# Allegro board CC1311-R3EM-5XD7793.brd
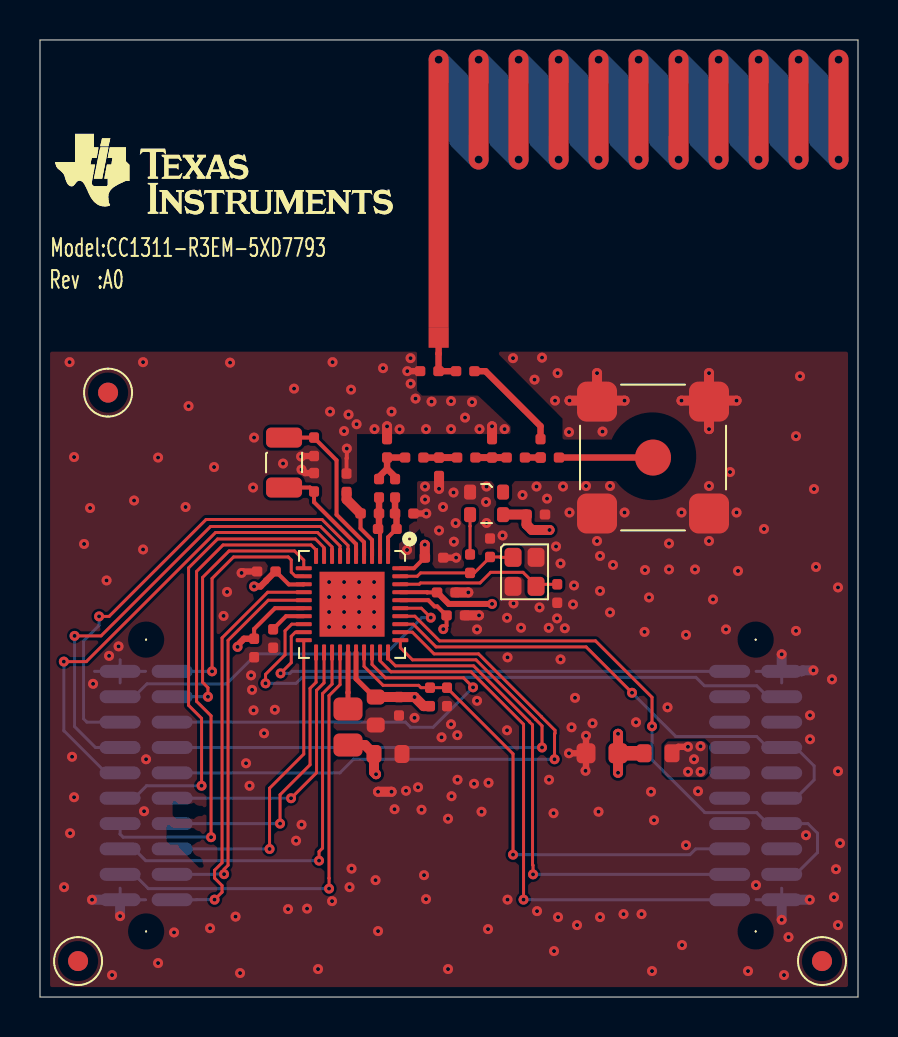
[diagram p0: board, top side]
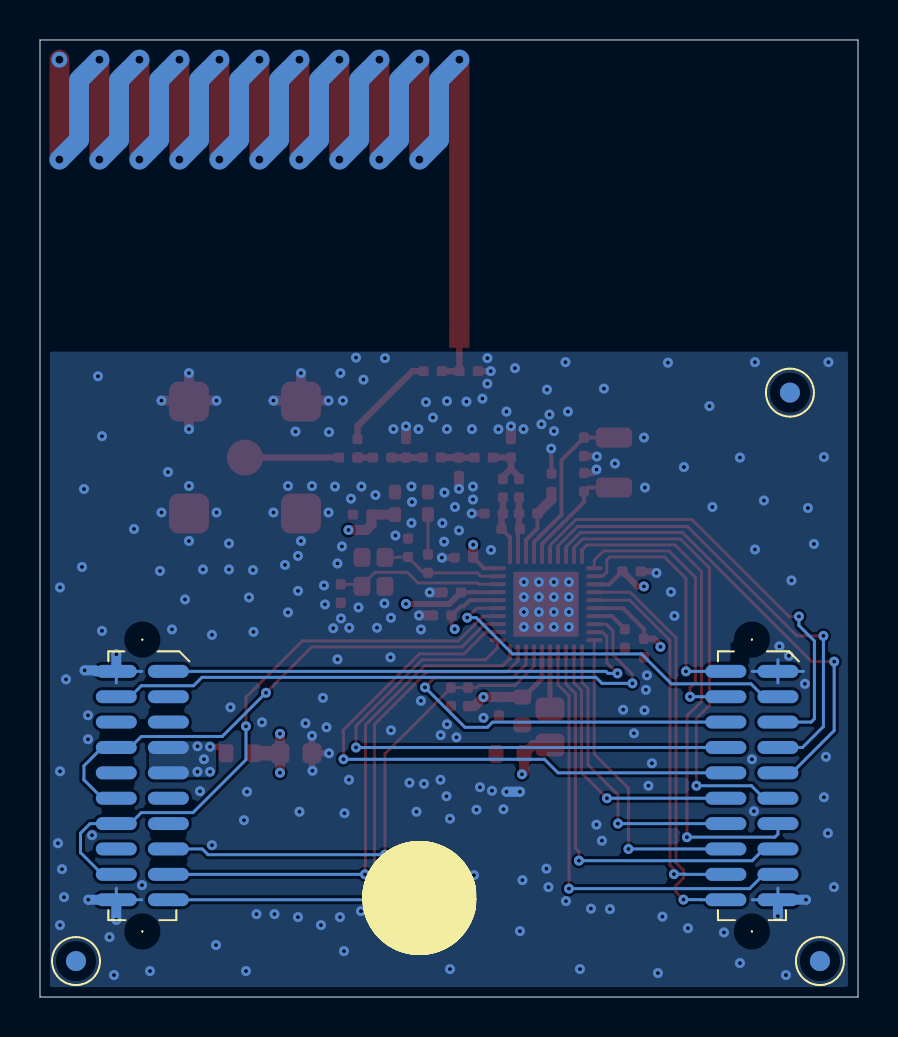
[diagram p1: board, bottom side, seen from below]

Outline 40.9 x 47.9 mm; copper layers: TOP, L2, L3, BOTTOM. Coordinates in mm from the lower left corner of the outline.
Outline path: 0,47.9 0,0 40.9,0 40.9,47.9 0,47.9

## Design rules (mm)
constraint set DEFAULT: min track width 0.15

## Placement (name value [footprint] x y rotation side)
A1  Antenna PCB helix 868/915MHz  [ANTENNA868_915MHZ_A2N]  19.93 32.99 0 top
C1  22uF  [CAPC1608X100A2N#2]  28.9 12.2 180 top
C11  3.6pF  [CAPC1005X60B2N]  17.75 24.2 0 top
C12  2.7pF  [CAPC1005X60B2N]  17.35 27 90 top
C13  6.2pF  [CAPC1005X60B2N]  19.95 26.08 90 top
C14  3pF  [CAPC1005X60B2N]  22.6 27.92 270 top
C15  100pF  [CAPC1005X60B2N]  24.25 27 180 top
C21  100pF  [CAPC1005X60B2N]  15.33 26.2 270 top
C22  3.6pF  [CAPC1005X60B2N]  16.95 25 90 top
C41  12pF  [CAPC1005X60B2N]  13.7 28 270 top
C51  12pF  [CAPC1005X60B2N]  13.7 25.3 90 top
C131  0.1uF  [CAPC1005X60B2N]  11.78 21.3 180 top
C221  0.1uF  [CAPC1005X60B2N]  10.71 17.93 270 top
C231  1uF  [CAPC1005X60B2N]  11.66 18.41 270 top
C331  22uF  [CAPC1608X100A2N]  16.7 12.16 0 top
C341  22uF  [CAPC1608X100A2N]  16.79 15.02 270 top
C342  0.1uF  [CAPC1005X60B2N]  17.95 15.01 270 top
C351  0.1uF  [CAPC1005X60B2N]  20.35 15.48 270 top
C441  0.1uF  [CAPC1005X60B2N]  20.33 19.1 0 top
C451  0.1uF  [CAPC1005X60B2N]  19.85 20.25 0 top
C461  7.5pF  [CAPC1005X60B2N]  25.86 20.66 270 top
C471  0.1uF  [CAPC1005X60B2N]  21.5 22.15 270 top
C472  0.1uF  [CAPC1005X60B2N]  24.33 24.15 0 top
C473  7.5pF  [CAPC1005X60B2N]  22.5 22.02 90 top
C481  0.1uF  [CAPC1005X60B2N]  19.24 21.99 0 top
FIDU1  FIDU_1MM  [FID100X115B]  1.9 1.8 0 top
FIDU2  FIDU_1MM  [FID100X115B]  39.1 1.8 0 top
FIDU3  FIDU_1MM  [FID100X115B]  3.4 30.25 0 top
FIDU4  FIDU_1MM  [FID100X115B]  1.9 1.8 180 bottom
FIDU5  FIDU_1MM  [FID100X115B]  39.1 1.8 180 bottom
FIDU6  FIDU_1MM  [FID100X115B]  3.4 30.25 180 bottom
FL1  BLM18HE152SN1  [FIL_BLM18HE152SN1DN]  30.2 12.2 0 top
J1  SMA-10V21-TGG  [HUSTSAN_SMA10V21TGGAN]  30.65 27 0 top
L11  27nH  [INDC1005X60D2N]  17.83 23.42 180 top
L12  7.5nH  [INDC1005X60D2N]  17.76 25 90 top
L13  6.8nH  [INDC1005X60D2N]  18.25 27 0 top
L14  6.8nH  [INDC1005X60D2N]  20.85 27 0 top
L15  1nH  [INDC1005X60D2N]  19.93 31.33 180 top
L21  7.5nH  [INDC1005X60D2N]  16.95 24.2 180 top
L331  6.8uH  [INDC2012X150A2N]  15.4 14.41 270 top
NOREF  -  []  1.75 43.2 0 top
NOREF#2  -  []  0 44.02 0 top
NOREF#3  -  []  29.31 0 90 top
NOREF#4  -  []  25.1 1.92 180 bottom
P1  SFM-110-02-S-D-A-K  [SAMTEC_SFM11002AN]  4 16.3 0 bottom
P2  SFM-110-02-S-D-A-K  [SAMTEC_SFM11002AN]  34.48 16.3 0 bottom
R11  0  [RESC1005X40B2N]  25.95 27 180 top
R12  0  [RESC1005X40B2N]  25.03 27 90 top
R13  0  [RESC1005X40B2N]  20.8 31.32 0 top
R351  100k  [RESC1005X40B2N]  19.5 15.48 270 top
U1  CC1311R31T0RKPR  [QFNFC40P500X500X100-41A2N]  17.4 22.08 180 top
Y1  32.768kHz  [XTAL_TZ1166C_B2N]  12.2 28 270 top
Y2  48MHz  [OSCCC200X160X50-4A2N]  23.66 22 270 top
Y3  48MHz  [OSC_TG2016SBN_A2N]  23.16 25.27 180 top

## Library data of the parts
A1 = ANTENNA: User Part Number: #PN
C1 C331 C341 = CAPACITOR: User Part Number: #PN; alternate symbols: (CAPC1608X100A2L,CAPC1608X100A2M)
C11-C15 C21 C22 C41 C51 C131 C221 C231 C342 C351 C441 C451 C461 C471-C473 C481 = CAPACITOR: User Part Number: #PN
FIDU1-FIDU6 = FIDMARK
FL1 = FILTER_2PIN: alternate symbols: (FIL_BLM18HE152SN1DL,FIL_BLM18HE152SN1DM)
J1 = CONN_COAX_1+4: alternate symbols: (HUSTSAN_SMA10V21TGGL,HUSTSAN_SMA10V21TGGM)
L11-L14 L21 = INDUCTOR_HOR_1_2: User Part Number: #PN
L15 = INDUCTOR_HOR_1_2: User Part Number: #PN; alternate symbols: (INDC1005X60C2L,INDC1005X60C2M)
L331 = INDUCTOR: User Part Number: #PN; alternate symbols: (INDC2012X150A2L,INDC2012X150A2M)
P1 P2 = CONN_HEADER_2X10_P_S: alternate symbols: (SAMTEC_SFM11002AL,SAMTEC_SFM11002AM)
R11-R13 R351 = RESISTOR: User Part Number: #PN
U1 = IC_RF_CC1311R1F32TRKPR_VQFN40: User Part Number: #PN; alternate symbols: (QFNFC40P500X500X100-41A2L,QFNFC40P500X500X100-41A2M)
Y1 = XTAL: User Part Number: #PN; alternate symbols: (XTAL_TZ1166C_B2L,XTAL_TZ1166C_B2M)
Y2 = XTAL_4_V3: User Part Number: #PN; alternate symbols: (OSCCC200X160X50-4A2L,OSCCC200X160X50-4A2M)
Y3 = XTAL_GEN: User Part Number: #PN; alternate symbols: (OSC_TG2016SBN_A2L,OSC_TG2016SBN_A2M)

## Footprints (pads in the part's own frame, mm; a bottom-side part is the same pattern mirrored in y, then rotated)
ANTENNA868_915MHZ_A2N
  rect 1x1 smd: 1(0,0)
CAPC1005X60B2N
  custom 0.125x0.125 smd: 1(0,0) 2(0.924,0)
CAPC1608X100A2N
  custom 0.188x0.188 smd: 1(0,0) 2(1.4,0)
CAPC1608X100A2N#2
  custom 0.237x0.237 smd: 1(0,0) 2(1.6,0)
FID100X115B
  round 1 smd: 1(0,0)
FIL_BLM18HE152SN1DN
  custom 0.188x0.188 smd: 1(0,0) 2(1.4,0)
HUSTSAN_SMA10V21TGGAN
  round 1.801 smd: 1(0,0)
  custom 0.5x0.5 smd: 2(-2.8,-2.8) 3(2.8,-2.8) 4(2.8,2.8) 5(-2.8,2.8)
INDC1005X60D2N
  custom 0.125x0.125 smd: 1(0,0) 2(0.924,0)
INDC2012X150A2N
  custom 0.287x0.287 smd: 1(0,0) 2(1.8,0)
OSC_TG2016SBN_A2N
  custom 0.15x0.15 smd: 1(0,0) 2(1.65,0) 3(1.65,1.13) 4(0,1.13)
OSCCC200X160X50-4A2N
  custom 0.212x0.212 smd: 1(0,0) 2(1.45,0) 3(1.45,1.15) 4(0,1.15)
QFNFC40P500X500X100-41A2N
  custom 0.05x0.05 smd: 1(0,0) 2(0.4,0) 3(0.8,0) 4(1.2,0) 5(1.6,0) 6(2,0) 7(2.4,0) 8(2.8,0) 9(3.2,0) 10(3.6,0) 11(4.215,0.615) 12(4.215,1.015) 13(4.215,1.415) 14(4.215,1.815) 15(4.215,2.215) 16(4.215,2.615) 17(4.215,3.015) 18(4.215,3.415) 19(4.215,3.815) 20(4.215,4.215) 21(3.6,4.83) 22(3.2,4.83) 23(2.8,4.83) 24(2.4,4.83) 25(2,4.83) 26(1.6,4.83) 27(1.2,4.83) 28(0.8,4.83) 29(0.4,4.83) 30(0,4.83) 31(-0.615,4.215) 32(-0.615,3.815) 33(-0.615,3.415) 34(-0.615,3.015) 35(-0.615,2.615) 36(-0.615,2.215) 37(-0.615,1.815) 38(-0.615,1.415) 39(-0.615,1.015) 40(-0.615,0.615)
  rect 3.25x3.25 smd: 41(1.8,2.415)
RESC1005X40B2N
  custom 0.125x0.125 smd: 1(0,0) 2(0.924,0)
SAMTEC_SFM11002AN
  round 0.099 hole 1.501 unplated: (1.302,-1.588) (1.302,13.017)
  oval 2.05x0.65 smd: 1(0,0) 2(2.604,0) 3(0,1.27) 4(2.604,1.27) 5(0,2.54) 6(2.604,2.54) 7(0,3.81) 8(2.604,3.81) 9(0,5.08) 10(2.604,5.08) 11(0,6.35) 12(2.604,6.35) 13(0,7.62) 14(2.604,7.62) 15(0,8.89) 16(2.604,8.89) 17(0,10.16) 18(2.604,10.16) 19(0,11.43) 20(2.604,11.43)
XTAL_TZ1166C_B2N
  custom 0.25x0.25 smd: 1(0,0) 2(2.5,0)

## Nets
GND: C1.2 C11.2 C12.2 C13.1 C14.1 C21.1 C41.2 C51.2 C131.2 C221.2 C231.2 C331.2 C341.2 C342.2 C351.2 C441.2 C451.2 C461.2 C472.2 C473.2 C481.2 J1.2 J1.3 J1.4 J1.5 L15.2 P1.1 P1.19 P2.2 P2.20 U1.41 Y2.2 Y2.4(GND#4) Y3.2
VDD_EB: FL1.2 P2.7 P2.9
VDDR: C331.1 C451.1 C481.1 L331.2 U1.37 U1.40
VDDS: C1.1 C131.1 C221.1 C341.1 C342.1 C441.1 C472.1 FL1.1 R351.2 U1.13 U1.16 U1.26 U1.36 Y3.4(VDD)
DCDC_SW: L331.1 U1.25
DIO_1: P1.5 U1.6
DIO_2: P1.7 U1.7
DIO_3: P1.9 U1.8
DIO_4: P1.11 U1.9
DIO_5: P1.13 U1.10
DIO_6: P1.4 U1.11
DIO_7: P1.2 U1.12
DIO_8: P1.20 U1.14
DIO_9: P1.18 U1.15(DIO_9)
DIO_10: P1.16 U1.20
DIO_11: P1.14 U1.21
DIO_12: P1.12 U1.22
DIO_13: P1.15 U1.23
DIO_14: P1.17 U1.24
DIO_15: P1.6 U1.28
DIO_16 / JTAG TDO: P2.19 U1.29
DIO_17 / JTAG TDI: P2.17 U1.30
DIO_18: P1.8 U1.31
DIO_19: P1.10 U1.32
DIO_20: P2.8 P2.12 U1.33
DIO_21: P2.14 P2.18 U1.34
DIO_22: P1.3 U1.35
JTAG_TCK: P2.1 U1.19
JTAG_TMS: P2.4 U1.18
NRESET: C351.1 P2.15 R351.1 U1.27
N485531: J1.1 R11.1
N485535: A1.1(FEED/GND_1) L15.1 R13.1
N485643: C22.1 L11.2 L21.1 U1.2
N485645: C11.1 L11.1 L12.1 U1.1
N485661: C12.1 C22.2 L12.2 L13.1
N485675: C13.2 L13.2 L14.1
N485699: C231.1 U1.17
N485701: C41.1 U1.4 Y1.1
N485707: C51.1 U1.5 Y1.2
N485827: C14.2 C15.2 L14.2
N485893: C15.1 R11.2 R12.1
N485901: R12.2 R13.2
N485927: C21.2 L21.2 U1.3
N485947: C461.1 U1.38 Y2.3
N499675: C471.2 C473.1 U1.39 Y2.1
N509134: C471.1 Y3.3

Pads without a net: FIDU1 1; FIDU2 1; FIDU3 1; FIDU4 1; FIDU5 1; FIDU6 1; P2 3 5 6 10 11 13 16; Y3 1

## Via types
v1: diameter 0.5, hole 0.2, TOP to BOTTOM, 281 vias
v2: diameter 0.8, hole 0.4, TOP to BOTTOM, 21 vias

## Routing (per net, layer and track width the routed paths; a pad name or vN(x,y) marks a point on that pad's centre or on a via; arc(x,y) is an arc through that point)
GND: length 40
  TOP w0.2: v1(15.34,27.45) 15.34,26.97 15.33,26.96 C21.1
  TOP w0.32: C51.2 13.25,26.22 v1(13.08,26.4) ; v1(27.3,13.08) C1.2 ; C1.2 v1(26.45,12.2) ; C1.2 27.3,11.35 v1(27.28,11.32) ; C131.2 10.15,21.3 v1(10.08,21.22) ; C41.2 13.08,27.08 v1(13.06,27.05) ; L15.2 v1(18.37,31.33) ; C481.2 v1(20.81,21.99) ; C11.2 v1(19.32,24.2)
  TOP w0.5: C12.2 v1(17.35,28.56) ; v1(32.08,29.85) 33.45,29.85 ; 33.45,29.85 v1(34.83,29.85) ; 33.45,29.85 v1(33.45,31.23) ; 33.45,29.85 J1.4 v1(33.45,28.42) ; 21.25,19.1 v1(21.95,19.1) ; 27.85,29.85 v1(29.23,29.85) ; 27.85,29.85 v1(27.85,31.23) ; 27.85,29.85 v1(26.48,29.85) ; v1(16.9,10.27) v1(17.58,10.27) ; C451.2 v1(21.42,20.25) ; C13.1 v1(19.95,25.44) ; C14.1 v1(22.6,28.56)
  L2 w0.5: v1(16.9,10.27) v1(17.58,10.27)
  L3 w0.5: v1(16.9,10.27) v1(17.58,10.27)
  BOTTOM w0.15: P1.1 5.28,16.3 ; P1.1 2.73,16.3 ; P1.1 4,16.88 ; P1.1 4,15.72 ; 5.28,4.87 P1.19 4,5.45 ; 35.81,4.87 P2.20 37.09,5.45 ; 35.81,16.3 P2.2 37.09,15.72
  BOTTOM w0.5: v1(37.09,3.87) P2.20 v1(38.49,4.87) ; v1(4,4.05) P1.19 v1(2.6,4.87) ; v1(16.9,10.27) v1(17.58,10.27) ; v1(38.67,16.35) 38.13,16.35 38.08,16.3 P2.2 v1(37.09,17.15)
  vias: v1(1.2,5.5) v1(1.48,31.77) v1(1.5,8.2) v1(1.6,12.02) v1(1.7,27.02) v1(1.7,10) v1(2.2,22.67) v1(2.5,24.47) v1(2.65,15.67) v1(3.33,20.85) v1(3.45,17.08) v1(3.6,1.1) v1(3.93,17.55) v1(4.7,24.85) v1(5.15,31.77) v1(5.15,22.4) v1(5.2,9.3) v1(5.3,11.9) v1(5.9,27) v1(5.9,1.7) v1(6.7,3.23) v1(7.28,24.52) v1(7.43,29.58) v1(8.5,3.44) v1(8.7,26.52) v1(9.18,19.08) v1(9.35,20.27) v1(9.5,31.75) v1(9.78,4.02) v1(10,1.2) v1(10.3,11.7) v1(10.55,16.1) v1(10.48,10.58) v1(10.6,15.38) v1(10.7,28) v1(10.65,25.5) v1(10.68,14.35) v1(11.2,13.2) v1(11.74,14.38) v1(12.15,26.7) v1(12.4,4.4) v1(12.7,30.45) v1(12.8,7.83) v1(13.08,8.62) v1(13.35,4.42) v1(13.9,1.4) v1(14.5,29.3) v1(14.46,20.77) v1(14.46,20.02) v1(14.46,19.27) v1(14.46,18.52) v1(14.63,31.77) v1(14.6,4.8) v1(15.2,28.33) v1(15.21,20.77) v1(15.21,20.02) v1(15.21,19.27) v1(15.21,18.52) v1(15.43,29.15) v1(15.55,30.4) v1(15.48,5.5) v1(15.58,6.42) v1(15.83,28.67) v1(15.96,20.77) v1(15.96,20.02) v1(15.96,19.27) v1(15.96,18.52) v1(16.73,28.42) v1(16.71,20.77) v1(16.71,20.02) v1(16.71,19.27) v1(16.71,18.52) v1(16.78,5.85) v1(16.9,3.3) v1(17.15,31.47) v1(17.58,29.3) v1(17.73,9.4) v1(17.98,28.42) v1(18.35,22.38) v1(18.3,10.32) v1(18.53,31.97) v1(18.53,30.7) v1(18.73,13.97) v1(18.78,29.95) v1(18.9,10.5) v1(19.08,9.38) v1(19.25,25.55) v1(19.25,24.9) v1(19.2,6.1) v1(19.3,28.42) v1(19.3,4.9) v1(19.58,29.8) v1(19.95,23.35) v1(20.08,13) v1(20.15,24.52) v1(20.4,8.92) v1(20.4,1.4) v1(20.55,29.83) v1(20.55,28.42) v1(20.55,13.65) v1(20.58,10.05) v1(20.68,25.25) v1(20.7,22.79) v1(20.78,23.72) v1(20.87,13.11) v1(20.88,10.88) v1(21.25,29) v1(21.6,29.77) v1(21.7,10.67) v1(21.85,18.4) v1(21.85,14.83) v1(21.98,28.42) v1(22.08,9.27) v1(22.33,25.55) v1(22.3,24.77) v1(22.33,23.72) v1(22.43,10.72) v1(22.4,3.4) v1(23.13,23.1) v1(23.23,28.42) v1(23.35,18.98) v1(23.35,13.35) v1(23.38,17) v1(23.38,4.88) v1(23.65,31.97) v1(23.68,19.7) v1(24.05,18.48) v1(24.13,25.12) v1(24.73,30.9) v1(24.83,25.55) v1(24.85,4.3) v1(24.98,19.5) v1(25.1,32) v1(25.35,24.94) v1(25.44,18.48) v1(25.45,10.88) v1(25.68,9.2) v1(25.7,2.3) v1(25.75,29.85) v1(25.8,22.55) v1(25.85,18.95) v1(25.88,31.23) v1(25.9,4) v1(26.03,21.7) v1(26.03,16.9) v1(26.15,25.55) v1(26.24,18.46) v1(26.45,28.27) v1(26.48,24.25) v1(26.58,13.5) v1(26.7,20.6) v1(26.65,19.65) v1(26.75,14.97) v1(26.85,3.6) v1(27.3,25.58) v1(27.63,13.7) v1(27.85,22.82) v1(27.93,9.27) v1(28,22.08) v1(28,20.33) v1(28,4) v1(28.13,28.3) v1(28.5,25.58) v1(28.5,19.25) v1(28.65,21.62) v1(29.23,24.25) v1(29.18,4.15) v1(29.8,13.75) v1(30.08,4.15) v1(30.25,21.37) v1(30.23,18.27) v1(30.45,20) v1(30.55,10.27) v1(30.6,1.3) v1(30.7,8.85) v1(31.45,22.7) v1(31.45,21.4) v1(31.38,14.5) v1(32.08,24.25) v1(32.1,2.6) v1(32.3,18.12) v1(32.3,7.6) v1(32.75,21.4) v1(32.9,10.3) v1(33.45,25.58) v1(33.45,22.82) v1(33.65,19.9) v1(34.3,18.4) v1(34.5,26.27) v1(34.83,24.25) v1(34.9,21.33) v1(35.4,1.3) v1(35.8,5.6) v1(36.2,23.42) v1(37.2,1.1) v1(37.43,3) v1(37.8,28.07) v1(37.8,18.33) v1(38,31.07) v1(38.3,8.1) v1(38.5,14.1) v1(38.5,12.9) v1(38.7,25.42) v1(38.8,21.52) v1(39.6,15.9) v1(39.7,5) v1(39.8,6.4) v1(39.9,20.5) v1(39.9,11.3) v1(39.9,3.6) v1(40,7.7)
VDD_EB: length 0.9
  TOP w0.32: v1(32.4,12.52) 31.93,12.52 FL1.2
  vias: v1(32.4,11.27) v1(32.7,11.9) v1(33.03,12.55) v1(33.03,11.27)
VDDR: length 27.6
  TOP w0.2: C451.1 19.36,20.25 19.35,20.26 U1.37 ; U1.40 18.7,21.46 19.23,21.99 C481.1
  TOP w0.3: C451.1 19.87,20.25 20.44,19.67 v1(22.6,19.67)
  TOP w0.5: v1(19.24,22.64) C481.1 ; L331.2 16.25,12.61 C331.1 16.7,11.25 v1(16.8,11.15)
  L3 w0.5: v1(16.8,11.15) 20.1,11.15 22.6,13.65 v1(22.6,19.67) 22.6,20.3 22.01,20.9 20.35,20.9 19.24,22.01 v1(19.24,22.64)
VDDS: length 79.7
  TOP w0.2: v1(20.17,18.41) 20.33,18.58 C441.1 20.32,19.1 19.87,19.55 19.73,19.55 19.42,19.86 U1.36 ; U1.13 13.18,20.65 12.44,20.65 11.79,21.3 C131.1 ; U1.16 11.75,19.46 10.71,18.42 C221.1
  TOP w0.25: C341.1 16.71,15.02 15.8,15.92 15.8,17.24
  TOP w0.32: C131.1 11.77,21.3 11.31,20.85 11.31,20.83 11.03,20.55 v1(10.7,20.55) ; C221.1 10.2,17.93 9.88,17.61 v1(9.88,17.52)
  TOP w0.5: v1(25.48,23.38) 24.6,23.38 24.33,23.64 C472.1 23.16,24.15 Y3.4 ; v1(28.9,11.22) C1.1 v1(28.9,13.17) ; C341.1 17.95,15.02 C342.1 v1(18.73,15.01) 19.18,14.56 R351.2
  TOP w0.73: FL1.1 C1.1
  L3 w0.15: 27.35,21.5 27.35,21.33
  L3 w0.5: 27.35,21.33 27.35,18.77 28.9,17.22 v1(28.9,13.17) ; 16.54,14.57 15.95,13.98 15.95,7.98 ; 16.54,14.57 16.54,14.79 v1(20.17,18.41) ; 16.54,14.57 18.28,14.57 v1(18.73,15.01) ; v1(10.7,20.55) 10.26,20.11 10.26,19.83 9.88,19.45 v1(9.88,17.52) 9.88,13.16 12.43,10.6 12.82,10.6 13.2,10.22 13.2,9.83 15.06,7.98 15.95,7.98 ; v1(28.9,11.22) 25.66,7.98 15.95,7.98 ; 27.35,21.5 27.35,22.13 26.11,23.38 v1(25.48,23.38)
DCDC_SW: length 2.8
  TOP w0.25: L331.1 15.4,15.24 15.4,15.24 15.4,17.24
DIO_1: length 22.9
  TOP w0.15: U1.6 15.4,22.6 14.1,23.9 8.31,23.9 3.45,19.05 v1(2.95,19.05)
  BOTTOM w0.15: v1(2.95,19.05) 2.95,18.6 2.18,17.82 2.18,13.93 2.34,13.76 P1.5
DIO_2: length 23.7
  TOP w0.15: U1.7 15,22.58 14.03,23.55 8.53,23.55 3.05,18.08 v1(1.73,18.08)
  BOTTOM w0.15: P1.7 2.78,12.49 1.73,13.54 v1(1.73,18.08)
DIO_3: length 24
  TOP w0.15: v1(1.19,16.79) 2.32,16.79 8.78,23.25 13.88,23.25 14.6,22.52 U1.8
  BOTTOM w0.15: P1.9 3.3,11.22 1.19,13.33 v1(1.19,16.79)
DIO_4: length 23.5
  TOP w0.15: U1.9 14.2,22.49 13.77,22.92 8.88,22.92 7.43,21.47 7.43,14.6 8.08,13.95 v1(8.08,10.58)
  BOTTOM w0.15: v1(8.08,10.58) 5.33,10.58 4.7,9.95 P1.11
DIO_5: length 25.7
  TOP w0.15: U1.10 13.8,22.38 13.55,22.62 9.15,22.62 7.83,21.3 7.83,14.8 8.55,14.07 v1(8.55,8)
  BOTTOM w0.15: v1(8.55,8) 4.16,8 4,8.15 P1.13
DIO_6: length 14.1
  TOP w0.15: U1.11 13.19,21.86 12.73,22.33 9.45,22.33 8.13,21 8.13,15.75 8.4,15.48 v1(8.4,15.03)
  BOTTOM w0.15: P1.4 v1(8.4,15.03)
DIO_7: length 12.4
  TOP w0.15: U1.12 12.77,21.06 12.56,21.27 12.56,21.88 12.41,22.02 9.68,22.02 8.6,20.95 v1(8.6,16.3)
  BOTTOM w0.15: P1.2 v1(8.6,16.3)
DIO_8: length 20.7
  TOP w0.15: U1.14 11.39,20.26 9.1,17.98 9.1,6.72 8.73,6.35 8.73,5.95 9.1,5.58 9.1,5.25 v1(8.73,4.88)
  BOTTOM w0.15: v1(8.73,4.88) 7.84,4.88 7.84,4.87 P1.20
DIO_9: length 19
  TOP w0.15: U1.15 11.41,19.86 9.4,17.85 9.4,6.6 9.2,6.4 v1(9.2,6.15)
  BOTTOM w0.15: v1(9.2,6.15) 8.67,6.15 8.66,6.14 P1.18
DIO_10: length 16
  TOP w0.15: U1.20 13.19,12.16 11.48,10.45 v1(11.48,7.41)
  BOTTOM w0.15: P1.16 v1(11.48,7.41)
DIO_11: length 14.7
  TOP w0.15: v1(12,8.68) 12,10.12 13.5,11.62 13.5,15.45 13.8,15.75 13.8,17.24
  BOTTOM w0.15: P1.14 v1(12,8.68)
DIO_12: length 13.9
  TOP w0.15: 14.2,17.24 14.2,15.72 13.83,15.35 13.83,11.22 v1(12.55,9.95)
  BOTTOM w0.15: P1.12 v1(12.55,9.95)
DIO_13: length 20.9
  TOP w0.15: v1(13.95,6.83) 13.95,7.28 14.13,7.45 14.13,15.19 14.6,15.66 14.6,17.24
  BOTTOM w0.15: v1(13.95,6.83) 5.29,6.83 4.7,7.41 P1.15
DIO_14: length 22.8
  TOP w0.15: v1(14.45,5.42) 14.45,5.95 14.45,5.95 14.45,15.08 15,15.64 15,17.24
  BOTTOM w0.15: P1.17 4.7,6.14 5.42,5.42 v1(14.45,5.42)
DIO_15: length 22.1
  TOP w0.15: 16.6,17.24 16.6,16.64 17.27,15.97 21.18,15.97 v1(21.65,15.5)
  BOTTOM w0.15: v1(21.65,15.5) 19.65,13.5 18.53,13.5 18.27,13.76 P1.6
DIO_16 / JTAG TDO: length 28
  TOP w0.15: 17,17.24 17,16.83 17.56,16.27 21.56,16.27 24.18,13.65 v1(24.18,4.88)
  BOTTOM w0.15: v1(24.18,4.88) 24.63,4.88 24.64,4.87 P2.19
DIO_17 / JTAG TDI: length 26.2
  TOP w0.15: v1(24.65,6.14) 24.65,6.59 24.63,6.62 24.63,13.62 24.48,13.77 24.48,13.78 21.68,16.58 17.77,16.58 17.4,16.94 17.4,17.24
  BOTTOM w0.15: P2.17 v1(24.65,6.14)
DIO_18: length 28.7
  TOP w0.15: U1.31 18.02,17.48 18.63,16.88 21.81,16.88 24.78,13.9 24.78,13.9 25.1,13.57 v1(25.1,12.49)
  BOTTOM w0.15: P1.8 v1(25.1,12.49)
DIO_19: length 30.6
  TOP w0.15: v1(25.73,11.9) 25.73,13.17 25.75,13.2 25.75,13.35 25.08,14.02 25.08,14.03 21.93,17.17 19.71,17.17 18.62,18.26 U1.32
  BOTTOM w0.15: P1.10 15,11.22 15.68,11.9 v1(25.73,11.9)
DIO_20: length 26.3
  TOP w0.15: U1.33 18.67,18.66 19.8,17.52 27.31,17.52 v1(29.6,15.23)
  BOTTOM w0.15: P2.12 37.79,9.95 38.71,10.87 38.71,11.57 37.79,12.49 P2.8 36.39,12.49 35.84,13.04 31.79,13.04 v1(29.6,15.23)
DIO_21: length 30.4
  TOP w0.15: v1(30.6,13.55) 30.6,15 27.78,17.83 19.98,17.83 18.74,19.06 U1.34
  BOTTOM w0.15: v1(30.6,13.55) 30.6,11.88 33.25,9.23 35.84,9.23 36.39,8.68 P2.14 38.4,8.68 38.88,8.2 38.88,7.23 37.79,6.14 P2.18
DIO_22: length 18.9
  TOP w0.15: v1(19.54,18.99) 19.07,19.46 U1.35
  BOTTOM w0.15: v1(19.54,18.99) 19.09,18.99 17.28,17.17 10.83,17.17 9.33,15.67 5.35,15.67 4.7,15.03 P1.3
JTAG_TCK: length 25.3
  TOP w0.15: U1.19 12.77,18.26 12.56,18.05 12.56,16.73 v1(12.03,16.2)
  BOTTOM w0.15: P2.1 12.6,16.3 12.5,16.2 v1(12.03,16.2)
JTAG_TMS: length 30.4
  TOP w0.15: v1(11.28,15.7) 11.28,16.15 12.25,17.13 12.25,18.33 12.59,18.66 U1.18
  BOTTOM w0.15: P2.4 36.39,15.03 35.84,15.58 33.22,15.58 32.8,16 13.1,16 12.8,15.7 v1(11.28,15.7)
Net_59:
  vias: v2(19.93,46.92) v2(21.93,41.92)
Net_60:
  vias: v2(37.93,46.92) v2(39.93,46.92) v2(39.93,41.92)
Net_61:
  vias: v2(35.93,46.92) v2(37.93,41.92)
Net_62:
  vias: v2(33.93,46.92) v2(35.93,41.92)
Net_63:
  vias: v2(31.93,46.92) v2(33.93,41.92)
Net_64:
  vias: v2(29.93,46.92) v2(31.93,41.92)
Net_65:
  vias: v2(27.93,46.92) v2(29.93,41.92)
Net_66:
  vias: v2(25.93,46.92) v2(27.93,41.92)
Net_67:
  vias: v2(23.93,46.92) v2(25.93,41.92)
Net_68:
  vias: v2(21.93,46.92) v2(23.93,41.92)
NRESET: length 26
  TOP w0.15: v1(23.65,7.12) 23.65,12.17 20.35,15.47 C351.1 R351.1 19.05,15.48 18.93,15.6 17.15,15.6 16.2,16.55 16.2,17.24
  BOTTOM w0.15: v1(23.65,7.12) 32.5,7.12 32.79,7.41 P2.15
N485531: length 4.7
  TOP w0.32: R11.1 J1.1
N485535: length 2.5
  TOP w0.32: A1.1 19.93,32.21 19.93,32.2 L15.1 19.93,31.32 R13.1
N485643: length 3
  TOP w0.2: L11.2 17,23.33 U1.2
  TOP w0.32: L11.2 16.95,23.47 L21.1 16.95,24.2 C22.1
N485645: length 3.1
  TOP w0.2: L11.1 17.82,23.42 17.41,23.01 17.41,23 U1.1
  TOP w0.32: L11.1 17.83,24.12 C11.1 17.75,25 L12.1
N485661: length 2.8
  TOP w0.32: 17.35,26.44 16.95,26.04 C22.2 ; 17.35,26.44 17.76,26.04 L12.2 ; 17.35,26.44 C12.1 L13.1
N485675: length 1.7
  TOP w0.15: L14.1 20.85,27
  TOP w0.32: C13.2 19.18,27 L13.2
  TOP w0.35: 20.85,27 C13.2
N485699: length 1.8
  TOP w0.2: U1.17 12.3,19.06 11.66,18.42 C231.1
N485701: length 8.5
  TOP w0.2: U1.4 16.2,22.77 14.83,24.14 14.83,26.86 13.7,27.99 C41.1 Y1.1
N485707: length 5.7
  TOP w0.2: Y1.2 13.5,25.5 C51.1 13.7,24.77 15.8,22.67 U1.5
N485827: length 1.6
  TOP w0.15: 22.6,27 C14.2 ; C15.2 23.33,27
  TOP w0.35: 23.33,27 C14.2 ; L14.2 22.6,27
N485893: length 0.8
  TOP w0.32: C15.1 R12.1 R11.2
N485901: length 5.1
  TOP w0.32: R13.2 22.28,31.32 25.03,28.57 R12.2
N485927: length 3.7
  TOP w0.2: U1.3 16.6,22.88 16.03,23.45 L21.2
  TOP w0.5: L21.2 15.33,24.9 C21.2
N485947: length 8.5
  TOP w0.15: C461.1 24.91,20.66 24.8,20.55 24.8,20.61 24.15,21.26 22.54,21.26 22.01,20.72 19.03,20.72 18.97,20.66 U1.38
N499675: length 6.1
  TOP w0.15: U1.39 18.86,21.06 19.03,21.23 C471.2 21.72,21.23 22.5,22.01 C473.1 23.01,22.02 23.03,22 Y2.1
N509134: length 2
  TOP w0.15: C471.1 21.5,23.56 Y3.3

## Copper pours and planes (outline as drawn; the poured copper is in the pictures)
GND on TOP: 0.5,0.5 0.5,32.3 18.85,32.3 18.85,30.35 19.1,30.1 21.9,30.1 23.53,28.58 23.53,28.17 15.85,28.17 15.85,23.2 16.35,22.7 17.9,22.7 17.9,22.2 13.48,22.2 13.48,17.58 18.2,17.58 18.2,21.6 19.2,21.6 19.2,23.2 19.08,23.2 18.85,23.7 18.85,25.83 28.8,25.83 32.8,27.29 28.59,27.91 28.58,27.9 26.13,27.9 26.13,28.95 22.8,32.3 40.4,32.3 40.4,0.5 ; 3 cut-outs
GND on TOP: 18.85,23.9 18.45,23.61 18.45,23.09 17.95,22.69 17.95,21.97 18.01,21.9 18.75,21.9 18.75,23.2 19.28,23.72
GND on BOTTOM: 0.5,0.5 0.5,32.3 40.4,32.3 40.4,0.5 ; 8 cut-outs
GND on L2: 0.5,0.5 0.5,32.3 40.4,32.3 40.4,0.5 ; 1 cut-out
GND on L3: 0.5,0.5 0.5,32.3 40.4,32.3 40.4,0.5
VDD_EB on TOP: 31.4,12.8 33.2,12.8 33.4,12.6 33.4,11.2 33.2,11 31.4,11 31.2,11.2 31.2,12.6
VDD_EB on BOTTOM: 32.3,12.8 35.2,12.8 35.45,12.55 35.45,11.15 35.3,11 32.35,11 32.1,11.25 32.1,12.6
Net_59 on BOTTOM (solid shape): 19.58,46.56 19.58,47.27 20.29,47.27 21.3,46.26 21.41,46.09 21.45,45.9 21.45,43.11 22.29,42.27 22.29,41.56 21.58,41.56 20.59,42.55 20.49,42.71 20.45,42.9 20.45,45.69
Net_60 on BOTTOM (solid shape): 37.58,46.56 37.58,47.27 38.29,47.27 39.3,46.26 39.41,46.09 39.45,45.9 39.45,43.11 40.29,42.27 40.29,41.56 39.58,41.56 38.59,42.55 38.48,42.71 38.45,42.9 38.45,45.69
Net_61 on BOTTOM (solid shape): 35.58,46.56 35.58,47.27 36.29,47.27 37.3,46.26 37.41,46.09 37.45,45.9 37.45,43.11 38.29,42.27 38.29,41.56 37.58,41.56 36.59,42.55 36.48,42.71 36.45,42.9 36.45,45.69
Net_62 on BOTTOM (solid shape): 33.58,46.56 33.58,47.27 34.29,47.27 35.3,46.26 35.41,46.09 35.45,45.9 35.45,43.11 36.28,42.27 36.28,41.56 35.58,41.56 34.59,42.55 34.48,42.71 34.45,42.9 34.45,45.69
Net_63 on BOTTOM (solid shape): 31.58,46.56 31.58,47.27 32.29,47.27 33.3,46.26 33.41,46.09 33.45,45.9 33.45,43.11 34.29,42.27 34.29,41.56 33.58,41.56 32.59,42.55 32.48,42.71 32.45,42.9 32.45,45.69
Net_64 on BOTTOM (solid shape): 29.58,46.56 29.58,47.27 30.29,47.27 31.3,46.26 31.41,46.09 31.45,45.9 31.45,43.11 32.28,42.27 32.28,41.56 31.58,41.56 30.59,42.55 30.48,42.71 30.45,42.9 30.45,45.69
Net_65 on BOTTOM (solid shape): 27.58,46.56 27.58,47.27 28.29,47.27 29.3,46.26 29.41,46.09 29.45,45.9 29.45,43.11 30.29,42.27 30.28,41.56 29.58,41.56 28.59,42.55 28.48,42.71 28.45,42.9 28.45,45.69
Net_66 on BOTTOM (solid shape): 25.58,46.56 25.58,47.27 26.29,47.27 27.3,46.26 27.41,46.09 27.45,45.9 27.45,43.11 28.29,42.27 28.29,41.56 27.58,41.56 26.59,42.55 26.48,42.71 26.45,42.9 26.45,45.69
Net_67 on BOTTOM (solid shape): 23.58,46.56 23.58,47.27 24.29,47.27 25.3,46.26 25.41,46.09 25.45,45.9 25.45,43.11 26.28,42.27 26.28,41.56 25.58,41.56 24.59,42.55 24.48,42.71 24.45,42.9 24.45,45.69
Net_68 on BOTTOM (solid shape): 21.58,46.56 21.58,47.27 22.29,47.27 23.3,46.26 23.41,46.09 23.45,45.9 23.45,43.11 24.29,42.27 24.29,41.56 23.58,41.56 22.59,42.55 22.48,42.71 22.45,42.9 22.45,45.69

Small or netless copper shapes (teardrops, artwork), in the pictures only: 11 on TOP

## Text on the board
Ref Des/Silkscreen Top: Rev  :A0 | Model:CC1311-R3EM-5XD7793
XSECTION_CHART: *  SURFACE - AIR 0 MM | L1: TOP CONDUCTOR - COPPER 0.035 MM | *  DIELECTRIC - FR-4 0.175 MM | L2: L2 PLANE - COPPER 0.018 MM | *  DIELECTRIC - FR-4 1.14 MM | L3: L3 PLANE - COPPER 0.018 MM | L4: BOTTOM CONDUCTOR - COPPER 0.035 MM | DESIGN CROSS SECTION CHART | ___________________________ | TOTAL THICKNESS 1.6 MM +/- 0.16 MM
DIMENSION: FIGURE | FINISHED_SIZE | 0.2 | 0.4 | 1.501 | DRILL CHART: TOP to BOTTOM | ALL UNITS ARE IN MILLIMETERS | PLATED | NON-PLATED | QTY | 273 | 25 | 21 | 4
